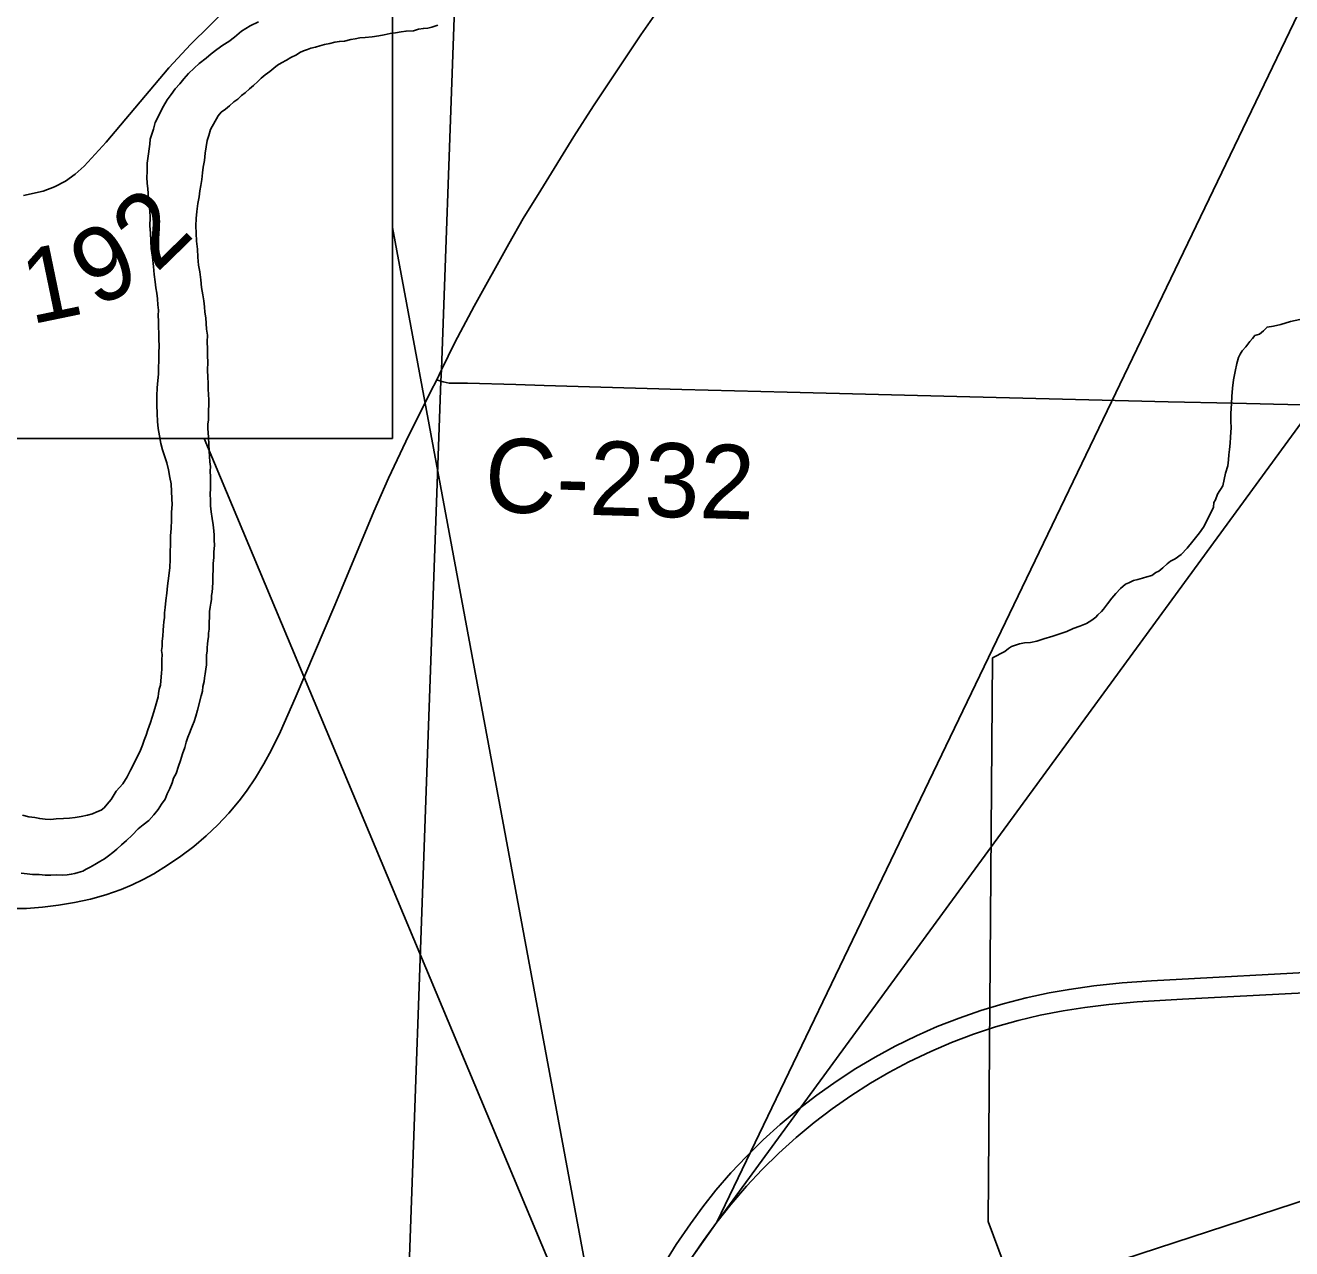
# Model space of a CAD drawing. Extents: x 0 to 64.8, y -5 to 22.
# Drawn here: x 5.41 to 6.381, y 18.132 to 19.071 of the extents above; entities that cross this region are included whole.
import ezdxf

# ---------------------------------------------------------------- set-up
doc = ezdxf.new("R2010")
doc.units = 0
for name, color, linetype in [('GM_X_County_Road', 7, 'Continuous'), ('GM_X_County_Road_Text', 7, 'Continuous'), ('GM_X_Major_River', 7, 'Continuous'), ('GM_X_Minor_River', 7, 'Continuous'), ('GM_X_Rail_Line', 7, 'Continuous'), ('GM_X_Township', 7, 'Continuous'), ('GM_X_Township_Road', 7, 'Continuous'), ('GM_X_Township_Road_Text', 7, 'Continuous'), ('GM_X_US_Route', 7, 'Continuous'), ('SH_Data', 7, 'Continuous'), ('SH_Masking', 7, 'Continuous'), ('SH_Text', 7, 'Continuous')]:
    doc.layers.add(name, color=color, linetype=linetype)

msp = doc.modelspace()

# ---------------------------------------------------------------- linework, layer by layer
at = {"layer": 'GM_X_County_Road'}
for points in [[(5.72509, 18.79874), (5.72837, 18.79765)], [(5.72837, 18.79765), (5.7301, 18.79707), (5.7346, 18.79625), (5.7401, 18.79608), (5.74877, 18.79615), (5.78578, 18.79519), (5.8075, 18.79435), (5.851, 18.79302), (5.91316, 18.79135), (5.99397, 18.78926), (6.13382, 18.7856), (6.28612, 18.78189), (6.33584, 18.78074), (6.36693, 18.77994), (6.43219, 18.77842), (6.49746, 18.77664), (6.55029, 18.7756), (6.61555, 18.77387), (6.69327, 18.77218), (6.73056, 18.77138), (6.73411, 18.77135)]]:
    msp.add_lwpolyline(points, dxfattribs=at)
at = {"layer": 'GM_X_Major_River'}
for points in [[(5.58845, 19.07342), (5.58191, 19.07015), (5.57535, 19.06612), (5.56993, 19.06169), (5.56568, 19.05836), (5.56105, 19.05543), (5.55641, 19.05211), (5.55215, 19.04879), (5.54828, 19.04546), (5.54286, 19.0414), (5.53898, 19.03769), (5.5347, 19.03361), (5.53119, 19.02951), (5.52806, 19.02578), (5.52456, 19.02206), (5.52141, 19.01757), (5.51828, 19.01346), (5.51551, 19.00859), (5.51312, 19.0037), (5.51113, 18.99995), (5.50915, 18.99619), (5.50789, 18.9909), (5.50666, 18.98713), (5.50544, 18.98336), (5.50497, 18.97957), (5.50358, 18.96858), (5.50312, 18.96479), (5.50304, 18.96138), (5.50297, 18.95834), (5.50288, 18.95416), (5.50315, 18.94922), (5.50344, 18.94541), (5.50374, 18.9416), (5.50402, 18.93704), (5.5043, 18.93285), (5.50496, 18.92828), (5.50523, 18.92333), (5.50508, 18.91688), (5.50572, 18.91116), (5.50597, 18.90546), (5.50621, 18.89938), (5.50721, 18.89289), (5.50781, 18.88566), (5.50843, 18.87957), (5.50906, 18.87385), (5.50972, 18.86928), (5.51038, 18.86509), (5.51105, 18.86089), (5.51133, 18.85633), (5.51161, 18.85214), (5.51152, 18.84796), (5.51181, 18.84378), (5.51171, 18.8396), (5.51196, 18.8339), (5.51187, 18.82972), (5.51214, 18.82477), (5.51202, 18.81946), (5.51189, 18.81338), (5.51176, 18.80807)], [(5.5781, 19.01895), (5.58159, 19.02191), (5.58469, 19.0245), (5.58779, 19.02746), (5.59051, 19.03006), (5.59361, 19.03265), (5.5971, 19.03523), (5.60019, 19.03782), (5.60291, 19.04004), (5.60599, 19.04187), (5.60984, 19.04406), (5.6133, 19.04588), (5.61753, 19.04807), (5.62024, 19.04991), (5.62292, 19.05099), (5.62599, 19.05205), (5.62867, 19.05313), (5.63211, 19.05382), (5.63556, 19.05488), (5.639, 19.05594), (5.6432, 19.0566), (5.64703, 19.05766), (5.65046, 19.05834), (5.65427, 19.05863), (5.65924, 19.05966), (5.66268, 19.06034), (5.66611, 19.06102), (5.6703, 19.06131), (5.67564, 19.06195), (5.6806, 19.06259), (5.68479, 19.06326), (5.68938, 19.0643), (5.69358, 19.06496), (5.69777, 19.06562), (5.70159, 19.0663), (5.7073, 19.06655), (5.71113, 19.0676), (5.71494, 19.06827), (5.71837, 19.06858), (5.72143, 19.06927), (5.72373, 19.06997), (5.72602, 19.07068)], [(5.54846, 18.58003), (5.54854, 18.58345), (5.54864, 18.58763), (5.54908, 18.59066), (5.54914, 18.59332), (5.5492, 18.59598), (5.54964, 18.59863), (5.55009, 18.60165), (5.55015, 18.60431), (5.5506, 18.60734), (5.55071, 18.61228), (5.55082, 18.61721), (5.55091, 18.62101), (5.55136, 18.62442), (5.55181, 18.62745), (5.55225, 18.6301), (5.55232, 18.63314), (5.55276, 18.63579), (5.55322, 18.6392), (5.55331, 18.64337), (5.55342, 18.64831), (5.55353, 18.65325), (5.55364, 18.6578), (5.55412, 18.66235), (5.55421, 18.66653), (5.55471, 18.67184), (5.55442, 18.67564), (5.5545, 18.67944), (5.5542, 18.68287), (5.55354, 18.68744), (5.55289, 18.6924), (5.55224, 18.69735), (5.55158, 18.70192), (5.55169, 18.70648), (5.55141, 18.71105), (5.5515, 18.71522), (5.55162, 18.72054), (5.55171, 18.72434), (5.55142, 18.72852), (5.55151, 18.73232), (5.5512, 18.73574), (5.55092, 18.73993), (5.55063, 18.74412), (5.5501, 18.75439), (5.54981, 18.75819), (5.5495, 18.76124), (5.54957, 18.76466), (5.55003, 18.76807), (5.55011, 18.77186), (5.5502, 18.77566), (5.55028, 18.77908), (5.55037, 18.78326), (5.55008, 18.78744), (5.5498, 18.79163), (5.5499, 18.79618), (5.54962, 18.80075), (5.54936, 18.80608), (5.5495, 18.81215), (5.54923, 18.81709), (5.54935, 18.82241), (5.54909, 18.82774), (5.54921, 18.83305), (5.54855, 18.83763), (5.54826, 18.84181), (5.54799, 18.84638), (5.54732, 18.85057), (5.54703, 18.85476), (5.54638, 18.85933), (5.54572, 18.86391), (5.54471, 18.86963), (5.54407, 18.87534), (5.54345, 18.88144), (5.54243, 18.88678), (5.54181, 18.89287), (5.54156, 18.89896), (5.54094, 18.90505), (5.5407, 18.91113), (5.54044, 18.91684), (5.54057, 18.92253), (5.54107, 18.92784), (5.54197, 18.9339), (5.54285, 18.9392), (5.54333, 18.94375), (5.54418, 18.94791), (5.54504, 18.95245), (5.54554, 18.95738), (5.54602, 18.96192), (5.54689, 18.96684), (5.5474, 18.97253), (5.54827, 18.97745), (5.54914, 18.98237), (5.55036, 18.98614), (5.55161, 18.99067), (5.55755, 19.00118), (5.55989, 19.00416), (5.56299, 19.00637), (5.56609, 19.00896), (5.56957, 19.01192), (5.57267, 19.01413), (5.57539, 19.01673), (5.5781, 19.01895)], [(5.51176, 18.80807), (5.51165, 18.80313), (5.51116, 18.7982), (5.51065, 18.79251), (5.51052, 18.78644), (5.51036, 18.77922), (5.51059, 18.77276), (5.51084, 18.76667), (5.51147, 18.76134), (5.51249, 18.75562), (5.5135, 18.7499), (5.51491, 18.74492), (5.51633, 18.74033), (5.51811, 18.73498), (5.51951, 18.72963), (5.52052, 18.7239), (5.52155, 18.71894), (5.52205, 18.70753), (5.52233, 18.70297), (5.52182, 18.69728), (5.52169, 18.6912), (5.52154, 18.68475), (5.52103, 18.67906), (5.52089, 18.6726), (5.52075, 18.66653), (5.52062, 18.66083), (5.52049, 18.65475), (5.51958, 18.64832), (5.51865, 18.64074), (5.51814, 18.63505), (5.51725, 18.62937), (5.51675, 18.62406), (5.51628, 18.6199), (5.51621, 18.61648), (5.51575, 18.61307), (5.51568, 18.61003), (5.51522, 18.60662), (5.51512, 18.60206), (5.51466, 18.59828), (5.51456, 18.5941), (5.51411, 18.59107), (5.51443, 18.58802), (5.51433, 18.58384), (5.51428, 18.58157), (5.51423, 18.57929), (5.51417, 18.57663), (5.5141, 18.57359), (5.51359, 18.56791), (5.51314, 18.5645), (5.51231, 18.56148), (5.51185, 18.55807), (5.51141, 18.55542), (5.51057, 18.55202), (5.50935, 18.54824), (5.50812, 18.54409), (5.50688, 18.53994), (5.50565, 18.53579), (5.50362, 18.53014), (5.50239, 18.52599), (5.50078, 18.52222), (5.49956, 18.51845), (5.49795, 18.51469), (5.49277, 18.50417), (5.49038, 18.49928), (5.4876, 18.49403), (5.48444, 18.48878), (5.47937, 18.4832), (5.47543, 18.47682), (5.4723, 18.4731), (5.46996, 18.47049), (5.46764, 18.46864), (5.46456, 18.46719), (5.46111, 18.46575), (5.45728, 18.4647), (5.45232, 18.46367), (5.44774, 18.46302), (5.44354, 18.46235), (5.43898, 18.46207), (5.43327, 18.46182), (5.42908, 18.46154), (5.4249, 18.46163), (5.42072, 18.46211), (5.41694, 18.46295), (5.41239, 18.46343), (5.40747, 18.46468)], [(5.40648, 18.42025), (5.41103, 18.41977), (5.4152, 18.4193), (5.42014, 18.41919), (5.42469, 18.4187), (5.42925, 18.4186), (5.43344, 18.41889), (5.438, 18.41878), (5.44181, 18.41908), (5.44486, 18.41939), (5.44754, 18.42009), (5.45021, 18.42079), (5.45366, 18.42185), (5.45635, 18.4233), (5.45943, 18.42476), (5.4629, 18.42696), (5.46675, 18.42915), (5.47022, 18.43135), (5.47331, 18.43356), (5.47679, 18.43614), (5.47989, 18.43873), (5.48339, 18.44207), (5.48727, 18.4454), (5.49154, 18.44948), (5.49621, 18.45432), (5.50008, 18.45727), (5.50434, 18.46059), (5.50824, 18.46506), (5.51137, 18.46917), (5.51413, 18.47329), (5.51687, 18.47703), (5.51849, 18.48117), (5.52048, 18.4853), (5.5221, 18.48945), (5.52332, 18.49322), (5.5253, 18.49659), (5.52695, 18.50225), (5.52857, 18.50678), (5.5302, 18.51168), (5.53183, 18.51658), (5.53307, 18.52073), (5.53429, 18.52451), (5.5355, 18.52752), (5.53671, 18.53091), (5.53792, 18.53354), (5.53912, 18.53655), (5.54036, 18.5407), (5.5416, 18.54523), (5.54451, 18.55619), (5.54535, 18.55997), (5.54581, 18.56338), (5.54665, 18.56716), (5.5471, 18.57019), (5.54755, 18.57322), (5.54801, 18.57663), (5.54846, 18.58003)]]:
    msp.add_lwpolyline(points, dxfattribs=at)
at = {"layer": 'GM_X_Minor_River'}
for points in [[(6.38709, 18.8451), (6.37983, 18.84337), (6.37256, 18.84126), (6.36682, 18.83987), (6.36187, 18.83922), (6.35914, 18.83624), (6.35604, 18.83366), (6.35259, 18.83259), (6.35064, 18.83036), (6.34869, 18.82813), (6.34556, 18.82402), (6.34283, 18.82104), (6.34125, 18.81842), (6.34005, 18.81578), (6.33881, 18.81125), (6.33753, 18.8052), (6.33624, 18.79878), (6.33534, 18.79234), (6.33482, 18.78589), (6.33469, 18.78057), (6.33414, 18.77299), (6.33401, 18.76691), (6.33428, 18.76197), (6.3342, 18.75855), (6.33373, 18.75476), (6.33363, 18.7502), (6.33314, 18.74528), (6.33267, 18.74111), (6.3322, 18.73732), (6.33172, 18.73277), (6.33007, 18.72711), (6.32795, 18.71728), (6.324, 18.71091), (6.32239, 18.70677), (6.3212, 18.70452), (6.32074, 18.70111), (6.31874, 18.69659), (6.31317, 18.6857), (6.31003, 18.68122), (6.30494, 18.67488), (6.30064, 18.66965), (6.29597, 18.66482), (6.29134, 18.66151), (6.28787, 18.65969), (6.28516, 18.65747), (6.28205, 18.6545), (6.27895, 18.65191), (6.27665, 18.65083), (6.27355, 18.64862), (6.26973, 18.64757), (6.26628, 18.64651), (6.26284, 18.64545), (6.2594, 18.64477), (6.25594, 18.64294), (6.25325, 18.64187), (6.24937, 18.63853), (6.24587, 18.63482), (6.24274, 18.63109), (6.23961, 18.62698), (6.23647, 18.62287), (6.23491, 18.62101), (6.23219, 18.61841), (6.23063, 18.61655), (6.22754, 18.61434), (6.2233, 18.61177), (6.21831, 18.60961), (6.21332, 18.60782), (6.20833, 18.60566), (6.20297, 18.60388), (6.19761, 18.6021), (6.19071, 18.59998), (6.18535, 18.59821), (6.18039, 18.59718), (6.17582, 18.59691), (6.172, 18.59623), (6.16893, 18.59516), (6.16587, 18.59409), (6.16356, 18.59263), (6.16084, 18.59041), (6.15122, 18.58531)], [(6.15122, 18.58531), (6.14797, 18.15303), (6.16016, 18.12008), (6.16499, 18.08159), (6.11693, 18.05761), (6.11184, 17.79748)]]:
    msp.add_lwpolyline(points, dxfattribs=at)
at = {"layer": 'GM_X_Rail_Line'}
msp.add_lwpolyline([(4.29132, 17.48235), (4.78304, 17.64156), (5.7936, 17.97429), (6.85366, 18.32082), (7.93472, 18.67204), (8.71777, 18.92606), (8.9, 18.98508)], dxfattribs=at)
at = {"layer": 'GM_X_Township'}
for points in [[(5.57574, 14.1), (5.60208, 14.77173), (5.62613, 15.79129), (5.65246, 16.99438), (5.65337, 17.03508), (5.68295, 17.54923), (5.68997, 17.72975), (5.69215, 17.79025), (5.72837, 18.79765), (5.72879, 18.80668), (5.75551, 19.55244), (5.75788, 19.61832), (5.76115, 19.7093), (5.76533, 19.84042), (5.65344, 19.8431), (5.46984, 19.84785), (5.43252, 19.84875), (5.389, 19.84945)], [(5.76533, 19.84042), (5.76115, 19.7093), (5.75788, 19.61832), (5.75551, 19.55244), (5.72879, 18.80668), (5.72837, 18.79765), (5.69215, 17.79025), (5.68997, 17.72975), (5.68295, 17.54923), (5.65337, 17.03508)]]:
    msp.add_lwpolyline(points, dxfattribs=at)
at = {"layer": 'GM_X_Township_Road'}
msp.add_lwpolyline([(5.40818, 18.94006), (5.42333, 18.94356), (5.43209, 18.94673), (5.44032, 18.95106), (5.44791, 18.95646), (5.45481, 18.96271), (5.47156, 18.98108), (5.51971, 19.03804), (5.53657, 19.0563), (5.56544, 19.08455), (5.57145, 19.09166), (5.57666, 19.09938), (5.58389, 19.11312), (5.60237, 19.15251), (5.61699, 19.18339), (5.63424, 19.2199), (5.64553, 19.24547), (5.66293, 19.28534), (5.71015, 19.38332), (5.71881, 19.40327), (5.72367, 19.41801), (5.73055, 19.44512), (5.75415, 19.54489), (5.75551, 19.55244)], dxfattribs=at)
at = {"layer": 'GM_X_US_Route'}
for points in [[(5.39822, 18.39318), (5.41049, 18.39323), (5.42284, 18.39423), (5.43514, 18.39573), (5.44737, 18.39776), (5.45946, 18.4004), (5.47137, 18.40374), (5.48305, 18.40782), (5.49162, 18.41136), (5.49998, 18.41536), (5.50812, 18.41979), (5.51867, 18.42628), (5.52886, 18.43332), (5.53874, 18.44079), (5.54819, 18.44879), (5.55717, 18.45731), (5.56567, 18.4663), (5.57365, 18.47576), (5.57923, 18.48318), (5.58611, 18.49347), (5.59249, 18.50409), (5.59842, 18.51497), (5.60527, 18.52887), (5.61658, 18.55442), (5.64699, 18.62591), (5.65213, 18.63821), (5.67692, 18.69762), (5.68823, 18.72322), (5.70148, 18.75136), (5.72027, 18.7896), (5.72509, 18.79874), (5.72878, 18.80633), (5.73897, 18.82732), (5.75381, 18.85525), (5.78046, 18.90302), (5.79149, 18.92254), (5.80493, 18.94423), (5.83024, 18.9855), (5.84545, 19.009), (5.88163, 19.06333), (5.8941, 19.08118)], [(5.89932, 18.11996), (5.90883, 18.13531), (5.91961, 18.15132), (5.92919, 18.16437), (5.93927, 18.17705), (5.95067, 18.19025), (5.96261, 18.20296), (5.97551, 18.2156), (5.98844, 18.22731), (6.00228, 18.23893), (6.01658, 18.24997), (6.03131, 18.26043), (6.04645, 18.2703), (6.06144, 18.27921), (6.07678, 18.28753), (6.09301, 18.29547), (6.10896, 18.30253), (6.12578, 18.30913), (6.14226, 18.31486), (6.15955, 18.3201), (6.17705, 18.32461), (6.19471, 18.3284), (6.21005, 18.3311), (6.22917, 18.33378), (6.25084, 18.33606), (6.27318, 18.33774), (6.41475, 18.3452)], [(5.92023, 18.12461), (5.92957, 18.1385), (5.93982, 18.15251), (5.95063, 18.1661), (5.96275, 18.18021), (5.97459, 18.19292), (5.98739, 18.20554), (6.00075, 18.21759), (6.01463, 18.22902), (6.02846, 18.23953), (6.04271, 18.24947), (6.05787, 18.25915), (6.0718, 18.26728), (6.08713, 18.27543), (6.10391, 18.2835), (6.11986, 18.29037), (6.13666, 18.29679), (6.15374, 18.30241), (6.17107, 18.30724), (6.18797, 18.31125), (6.20562, 18.3147), (6.22218, 18.31729), (6.24066, 18.31952), (6.26231, 18.32142), (6.29703, 18.3236), (6.57765, 18.33826)]]:
    msp.add_lwpolyline(points, dxfattribs=at)
at = {"layer": 'SH_Data'}
msp.add_lwpolyline([(5.86034, 18.00448), (5.87074, 18.02803), (5.88546, 18.06024), (5.9044, 18.09796), (5.92023, 18.12461), (5.93982, 18.15251)], dxfattribs=at)
at = {"layer": 'SH_Masking'}
msp.add_lwpolyline([(3.6186, 19.24378), (5.69117, 19.24378), (5.69117, 18.75378), (3.6186, 18.75378)], close=True, dxfattribs=at)
at = {"layer": 'SH_Text'}
for p, q in [((6.59875, 19.05422), (5.93982, 18.15251)), ((5.69117, 18.75378), (5.69117, 18.91555)), ((5.54686, 18.75378), (5.69117, 18.75378))]:
    msp.add_line(p, q, dxfattribs=at)
for points in [[(5.93982, 18.15251), (6.48, 19.27574)], [(5.69117, 18.91555), (5.86034, 18.00448), (5.54686, 18.75378)]]:
    msp.add_lwpolyline(points, dxfattribs=at)
msp.add_lwpolyline([(3.6186, 19.24378), (5.69117, 19.24378), (5.69117, 18.75378), (3.6186, 18.75378)], close=True, dxfattribs=at)

# ---------------------------------------------------------------- texts
at = {"layer": 'GM_X_County_Road_Text'}
msp.add_text('C-232', height=0.056818, rotation=358.34799, dxfattribs=at).set_placement((5.76136, 18.69746))
at = {"layer": 'GM_X_Township_Road_Text'}
for s, rotation, p in [('2', 44.26506, (5.51018, 18.88018)), ('9', 26.56609, (5.46334, 18.85348)), ('1', 11.68837, (5.41391, 18.84114))]:
    msp.add_text(s, height=0.05682, rotation=rotation, dxfattribs=at).set_placement(p)

doc.saveas('drawing.dxf')
